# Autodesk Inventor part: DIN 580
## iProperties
SaveDate: 2002-10-24
SaveTime: 13:41
TotalMass: 0.0 kg
TotalVolume: 0.0 mm^3
Author: Cor de Vlaming
Shininess: 64.0
Angle Display Precision: 2
Document Length Units: 11269
Document Angle Units: 11283
Document Time Units: 11279
Document Mass Units: 11290
Document Length Units Precision: 3
Document Angle Units Precision: 2
Compacted: True
PropertySet Name: _Private Model Information
Created: 2002-10
Part Number: DIN 580
Cost Center: 0.0 kg
Material: C15
Document SubType Name: Modeling
Designer: Cor de Vlaming
Authority: 0.0 mm^3
Control State: 0
Master: False
Checked Out: False
PropertySet Name: Design Tracking Control
Density: 0.0
Volumn: 0.0
Area: 0.0
PropertySet Name: Model Information
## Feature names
1. Sweep1
2. Revolution1
3. Extrusion1
4. Extrusion2
5. Chamfer1
6. Fillet1
